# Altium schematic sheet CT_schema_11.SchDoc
size 742 x 377 mm
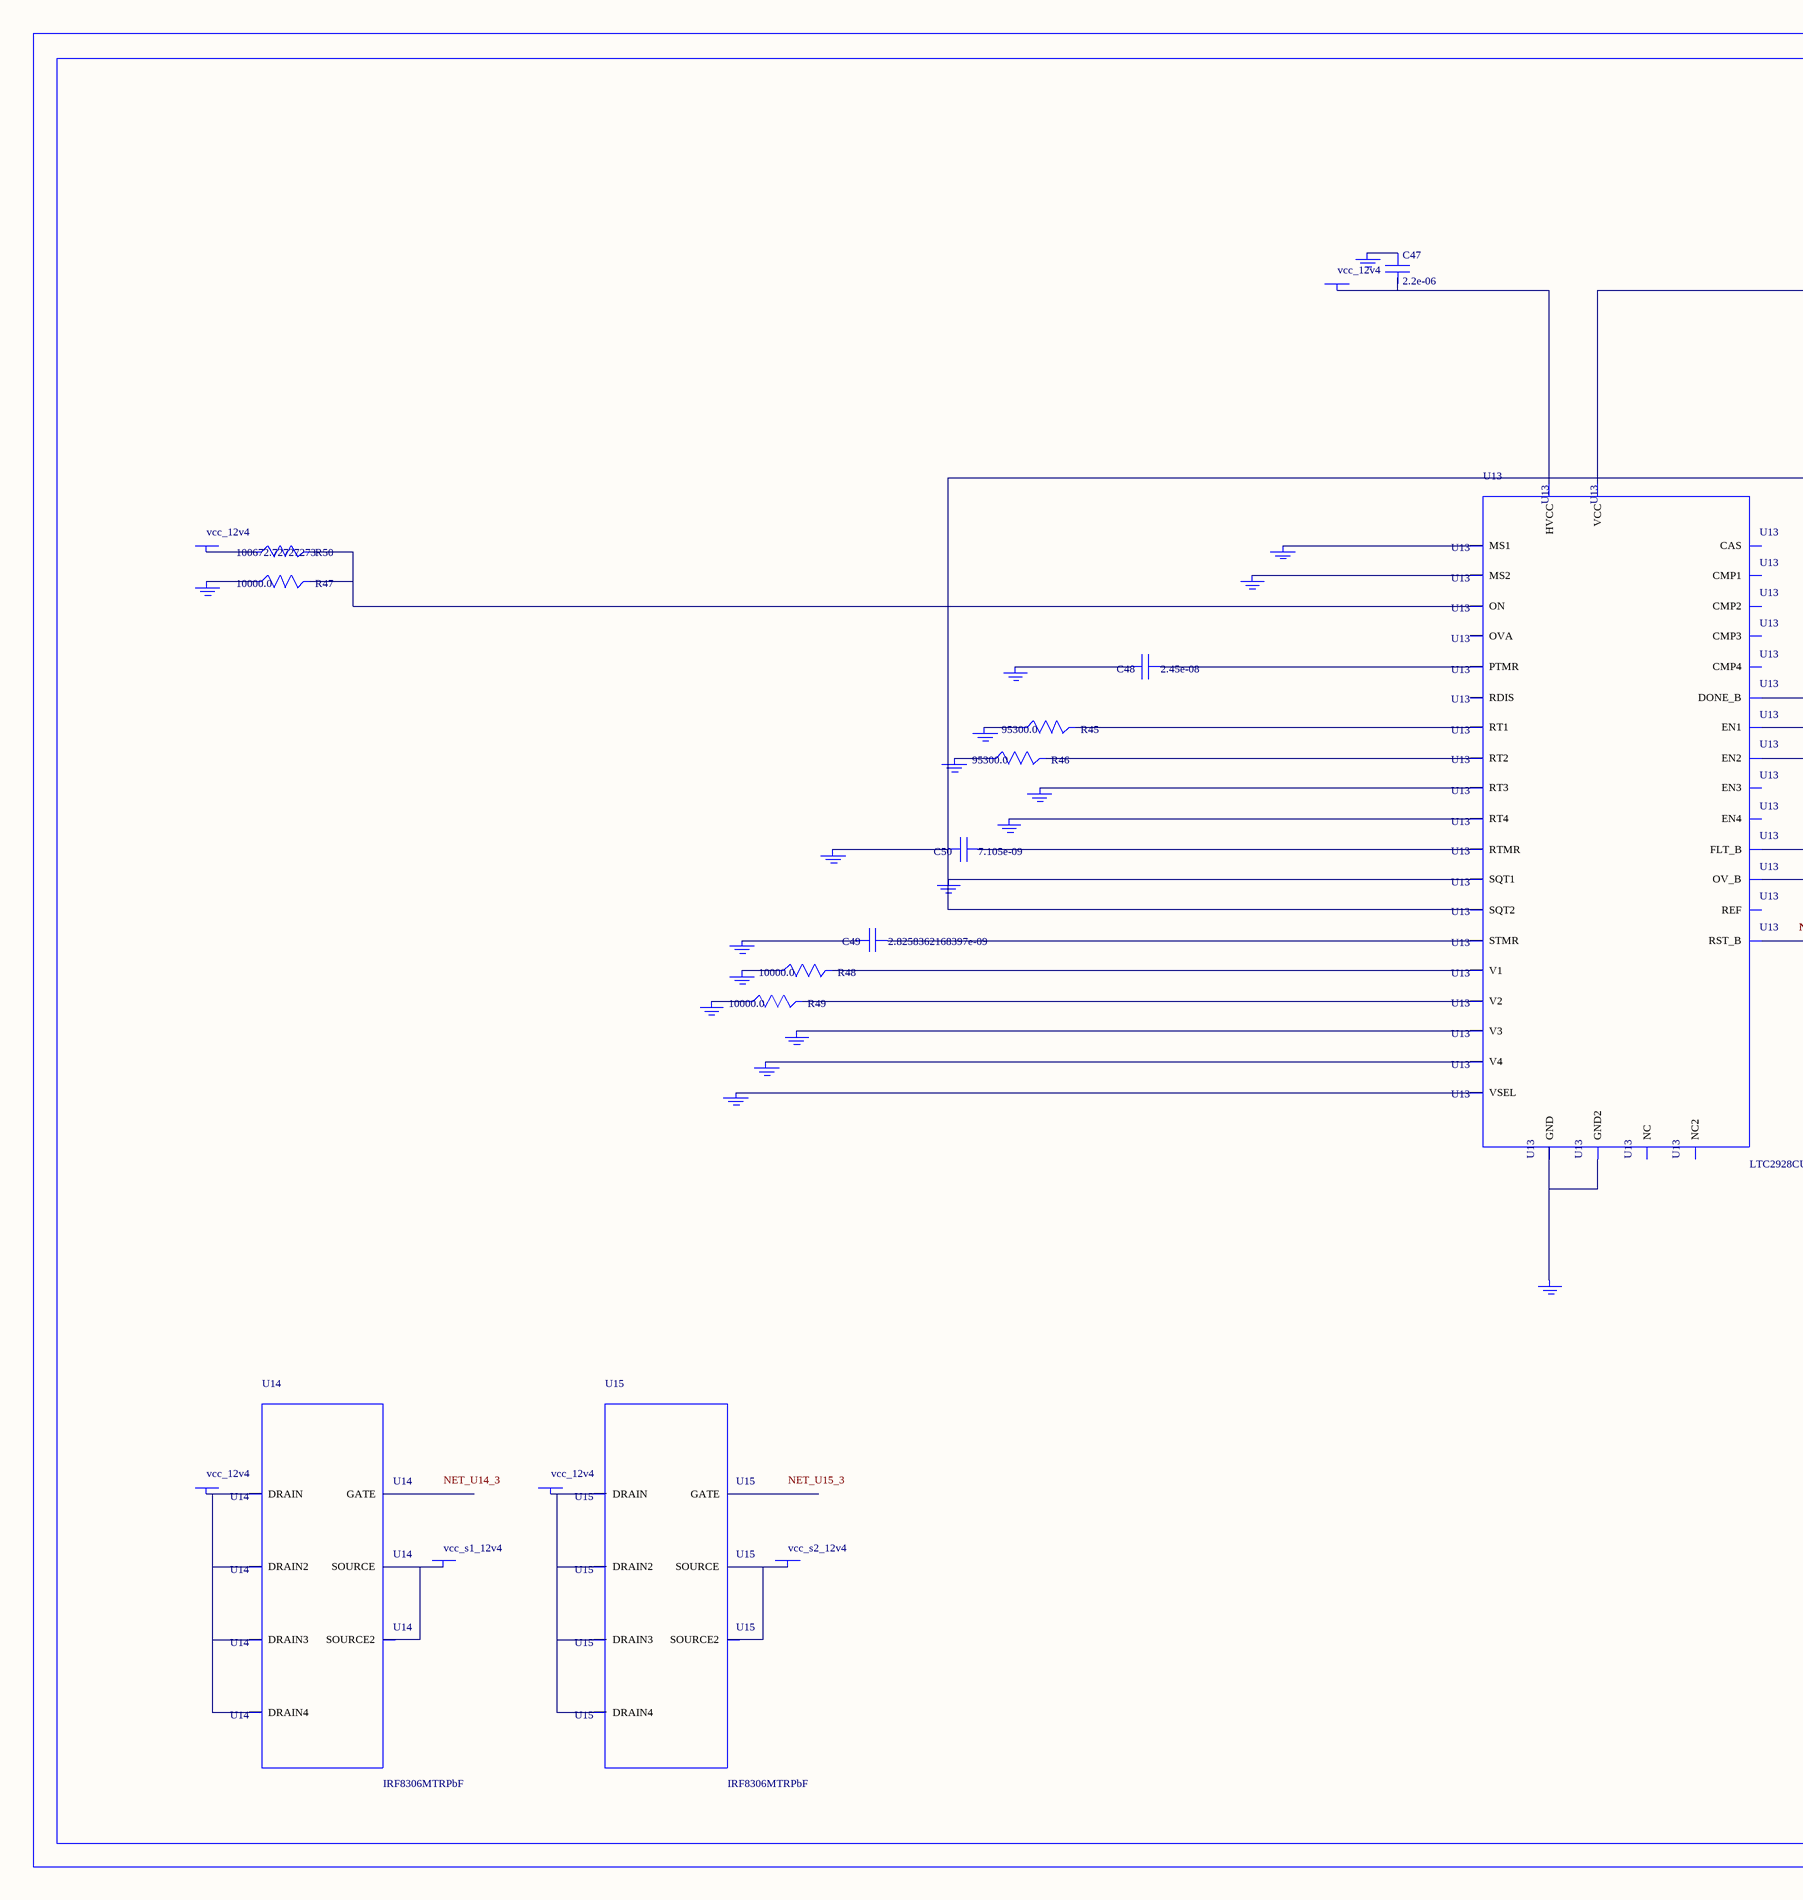
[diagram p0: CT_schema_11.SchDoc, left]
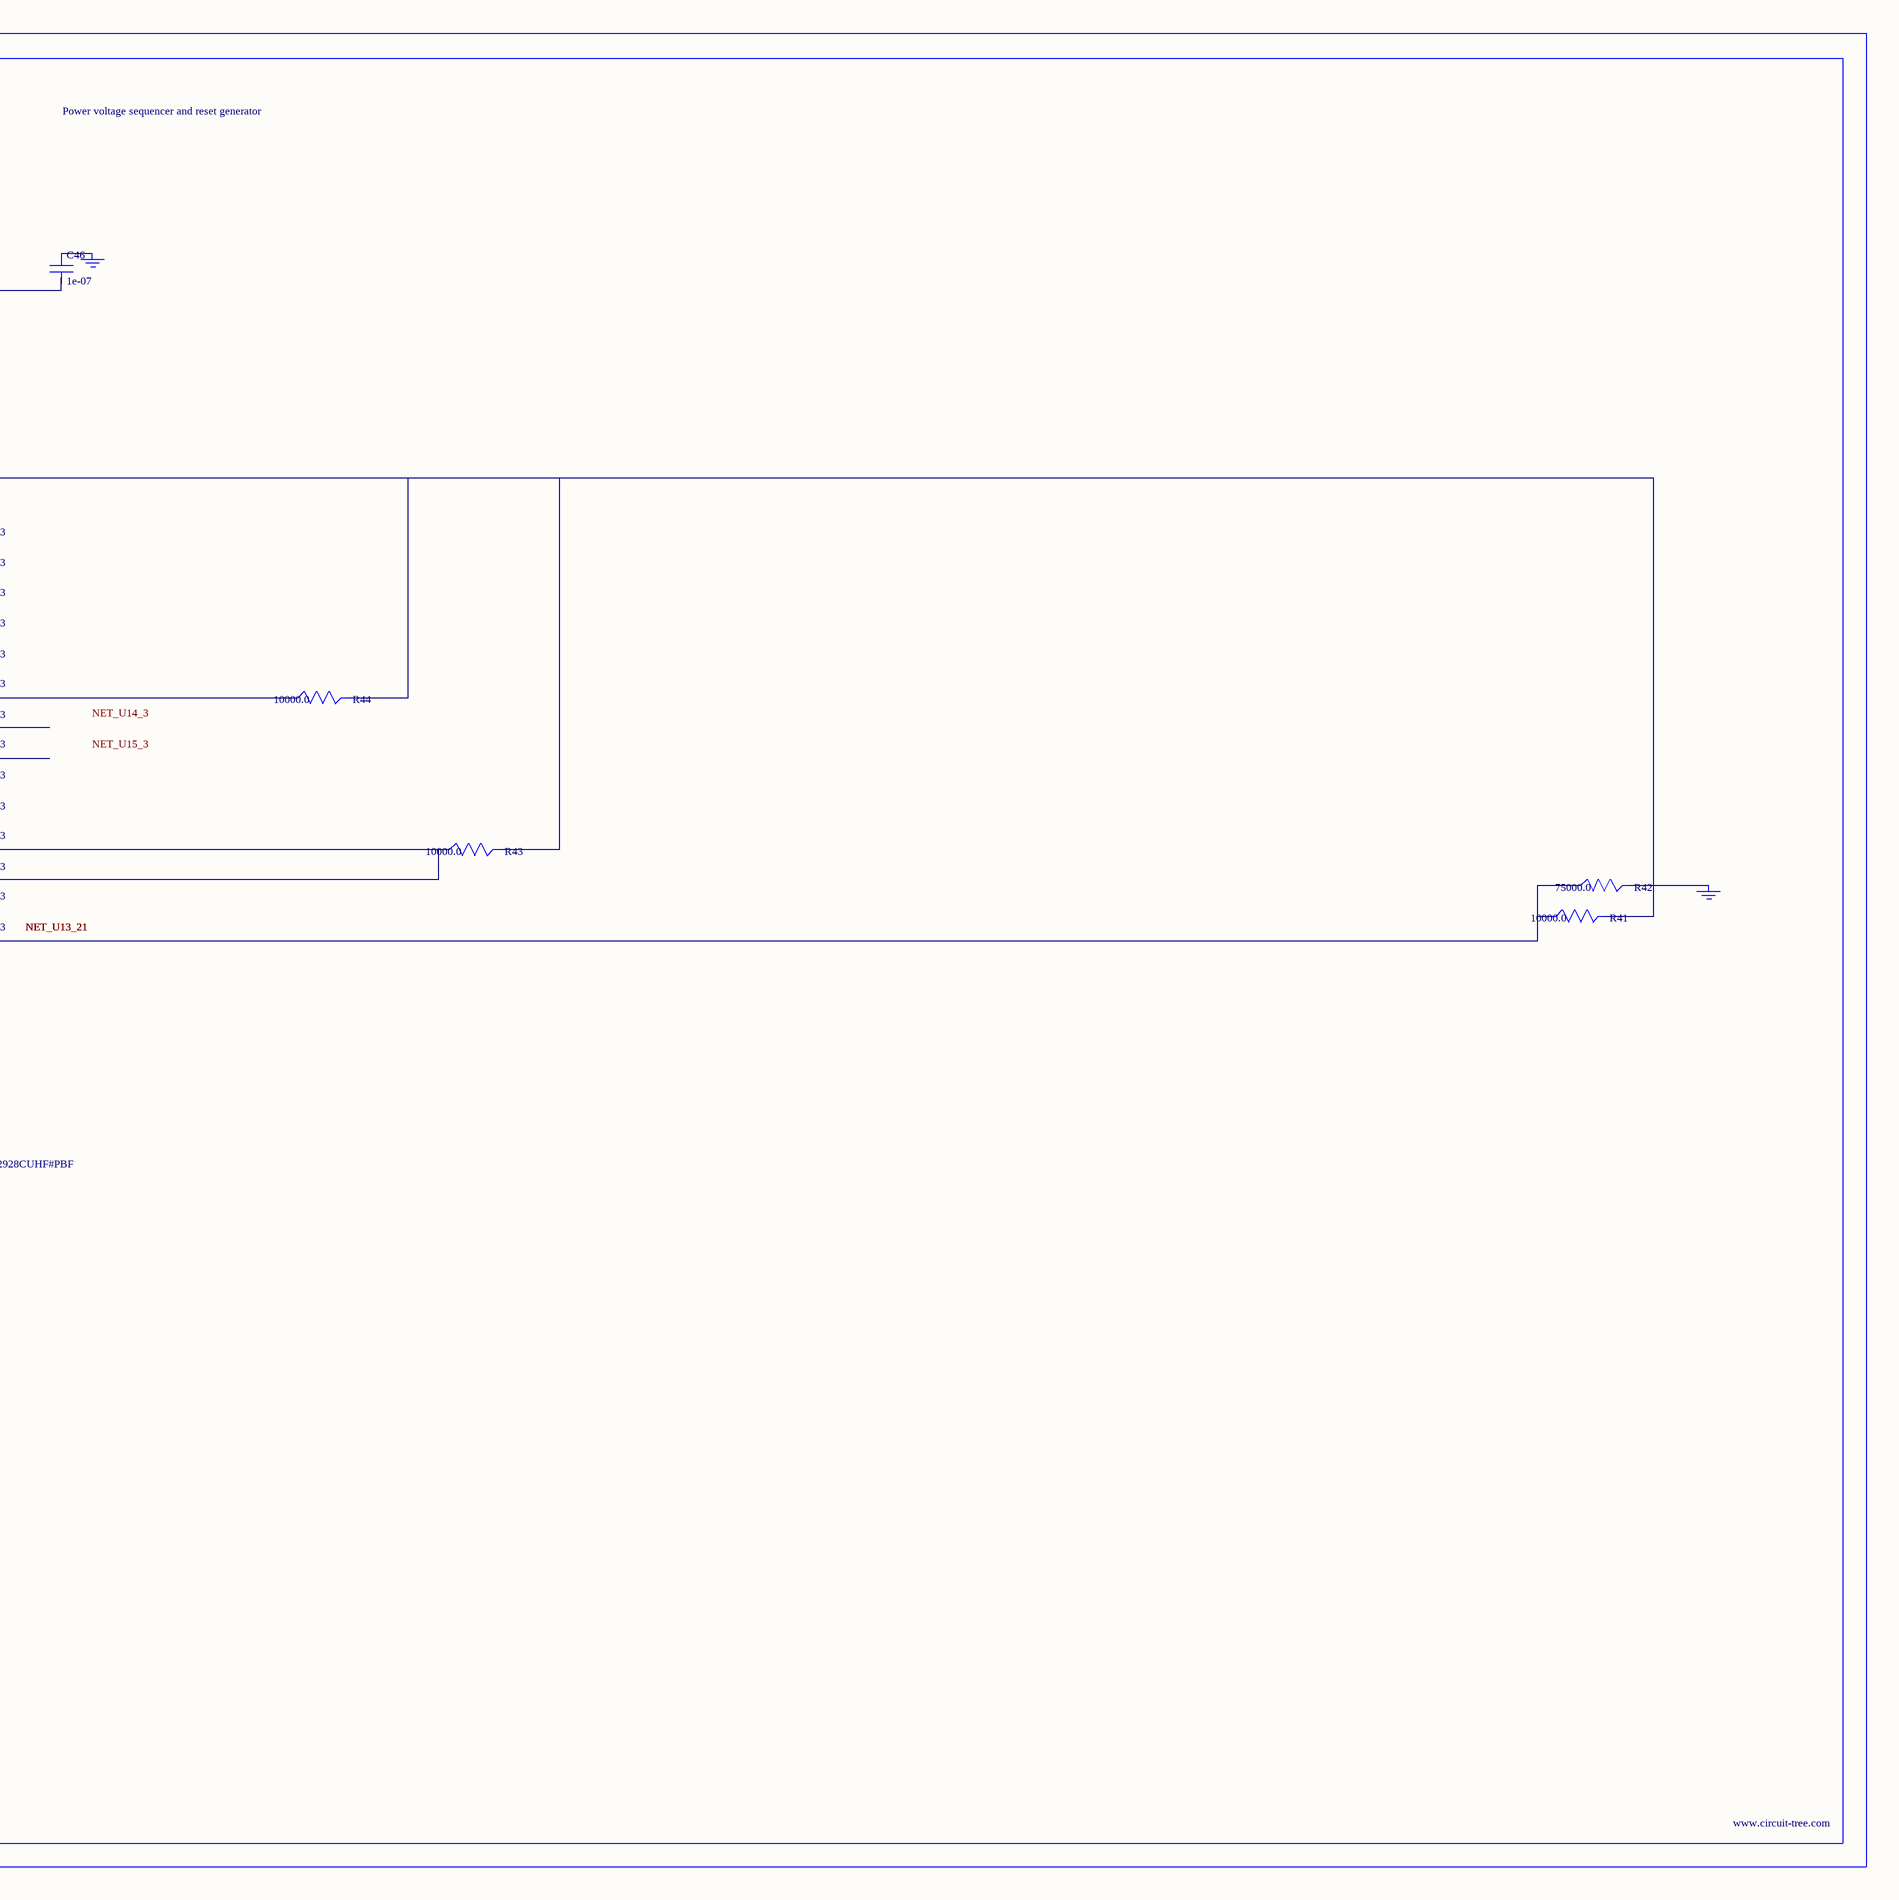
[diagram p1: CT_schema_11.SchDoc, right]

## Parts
BORDER10  (no value)
C46  1e-07  [C0402]
C47  2.2e-06  [C0603]
C48  2.45e-08  [R0603]
C49  2.8258362168397e-09  [R0603]
C50  7.105e-09  [R0603]
GND_INSTANCE_10_0  (no value)
GND_INSTANCE_10_1  (no value)
GND_INSTANCE_10_2  (no value)
GND_INSTANCE_10_3  (no value)
GND_INSTANCE_10_4  (no value)
GND_INSTANCE_10_5  (no value)
GND_INSTANCE_10_6  (no value)
GND_INSTANCE_10_7  (no value)
GND_INSTANCE_10_8  (no value)
GND_INSTANCE_10_9  (no value)
GND_INSTANCE_10_10  (no value)
GND_INSTANCE_10_11  (no value)
GND_INSTANCE_10_12  (no value)
GND_INSTANCE_10_13  (no value)
GND_INSTANCE_10_14  (no value)
GND_INSTANCE_10_15  (no value)
GND_INSTANCE_10_16  (no value)
GND_INSTANCE_10_17  (no value)
GND_INSTANCE_10_18  (no value)
GND_INSTANCE_10_19  (no value)
POWER_INSTANCE_10_0  vcc_12v4
POWER_INSTANCE_10_1  vcc_12v4
POWER_INSTANCE_10_2  vcc_12v4
POWER_INSTANCE_10_3  vcc_s1_12v4
POWER_INSTANCE_10_4  vcc_12v4
POWER_INSTANCE_10_5  vcc_s2_12v4
R41  10000.0  [R0603]
R42  75000.0  [R0603]
R43  10000.0  [R0603]
R44  10000.0  [R0603]
R45  95300.0  [R0603]
R46  95300.0  [R0603]
R47  10000.0  [R0603]
R48  10000.0  [R0603]
R49  10000.0  [R0603]
R50  100672.72727273  [R0603]
U13  LTC2928CUHF#PBF  [QFN-38_UHF]
U14  IRF8306MTRPbF  [IRF8306MTRPBF]
U15  IRF8306MTRPbF  [IRF8306MTRPBF]

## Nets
NetC46_1: C46.1 GND_INSTANCE_10_10.0(GND)
NetC46_2: C46.2 C50.2 GND_INSTANCE_10_5.0(GND) GND_INSTANCE_10_15.0(GND) R41.2 R43.2 R44.2 U13.10(SQT1) U13.11(SQT2) U13.22(VCC)
NetC47_1: C47.1 GND_INSTANCE_10_11.0(GND)
NetC47_2: C47.2 POWER_INSTANCE_10_1.0(PWR) U13.23(HVCC)
NetC48_1: C48.1 U13.27(PTMR)
NetC48_2: C48.2 GND_INSTANCE_10_14.0(GND)
NetC49_1: C49.1 U13.26(STMR)
NetC49_2: C49.2 GND_INSTANCE_10_13.0(GND)
NetC50_1: C50.1 U13.28(RTMR)
NetGND_INSTANCE_10_0_0: GND_INSTANCE_10_0.0(GND) R48.1
NetGND_INSTANCE_10_1_0: GND_INSTANCE_10_1.0(GND) R45.1
NetGND_INSTANCE_10_2_0: GND_INSTANCE_10_2.0(GND) R46.1
NetGND_INSTANCE_10_3_0: GND_INSTANCE_10_3.0(GND) U13.8(RT3)
NetGND_INSTANCE_10_4_0: GND_INSTANCE_10_4.0(GND) U13.9(RT4)
NetGND_INSTANCE_10_6_0: GND_INSTANCE_10_6.0(GND) U13.12(MS1)
NetGND_INSTANCE_10_7_0: GND_INSTANCE_10_7.0(GND) U13.13(MS2)
NetGND_INSTANCE_10_8_0: GND_INSTANCE_10_8.0(GND) R47.1
NetGND_INSTANCE_10_9_0: GND_INSTANCE_10_9.0(GND) R42.2
NetGND_INSTANCE_10_12_0: GND_INSTANCE_10_12.0(GND) U13.25(VSEL)
NetGND_INSTANCE_10_16_0: GND_INSTANCE_10_16.0(GND) U13.30(V4)
NetGND_INSTANCE_10_17_0: GND_INSTANCE_10_17.0(GND) U13.32(V3)
NetGND_INSTANCE_10_18_0: GND_INSTANCE_10_18.0(GND) R49.1
NetGND_INSTANCE_10_19_0: GND_INSTANCE_10_19.0(GND) U13.24(GND) U13.39(GND2)
NetPOWER_INSTANCE_10_0_0: POWER_INSTANCE_10_0.0(PWR) R50.1
NetPOWER_INSTANCE_10_2_0: POWER_INSTANCE_10_2.0(PWR) U14.1(DRAIN) U14.2(DRAIN2) U14.6(DRAIN3) U14.7(DRAIN4)
NetPOWER_INSTANCE_10_3_0: POWER_INSTANCE_10_3.0(PWR) U14.4(SOURCE) U14.5(SOURCE2)
NetPOWER_INSTANCE_10_4_0: POWER_INSTANCE_10_4.0(PWR) U15.1(DRAIN) U15.2(DRAIN2) U15.6(DRAIN3) U15.7(DRAIN4)
NetPOWER_INSTANCE_10_5_0: POWER_INSTANCE_10_5.0(PWR) U15.4(SOURCE) U15.5(SOURCE2)
NetR41_1: R41.1 R42.1 U13.21(RST_B)
NetR43_1: R43.1 U13.19(FLT_B) U13.20(OV_B)
NetR44_1: R44.1 U13.18(DONE_B)
NetR45_2: R45.2 U13.6(RT1)
NetR46_2: R46.2 U13.7(RT2)
NetR47_2: R47.2 R50.2 U13.16(ON)
NetR48_2: R48.2 U13.3(V1)
NetR49_2: R49.2 U13.38(V2)

Not connected (* = marked no-connect by the designer): U13 1(OVA) 2(EN1) 4(NC) 5(REF) 14(RDIS) 15(CAS) 17(NC2) 29(EN4) 31(EN3) 33(CMP3) 34(CMP4) 35(CMP1) 36(CMP2) 37(EN2); U14 3(GATE); U15 3(GATE)

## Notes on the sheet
- Labels drawn without touching a wire or pin: NET_U14_3, NET_U15_3

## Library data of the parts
BORDER10 = BORDER_PAGE10
C46 = C0402C104K3RACTU
C47 = GRM188R61H225KE1115D
C48 = C48
C49 = C49
C50 = C50
GND_INSTANCE_10_0-GND_INSTANCE_10_19 = GND
POWER_INSTANCE_10_0-POWER_INSTANCE_10_5 = PWR
R41 R43 R44 R47-R49 = RC0603JR-0710KL
R42 = RC0603JR-0775KL
R45 R46 = RC0603FR-0795K3L
R50 = R50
